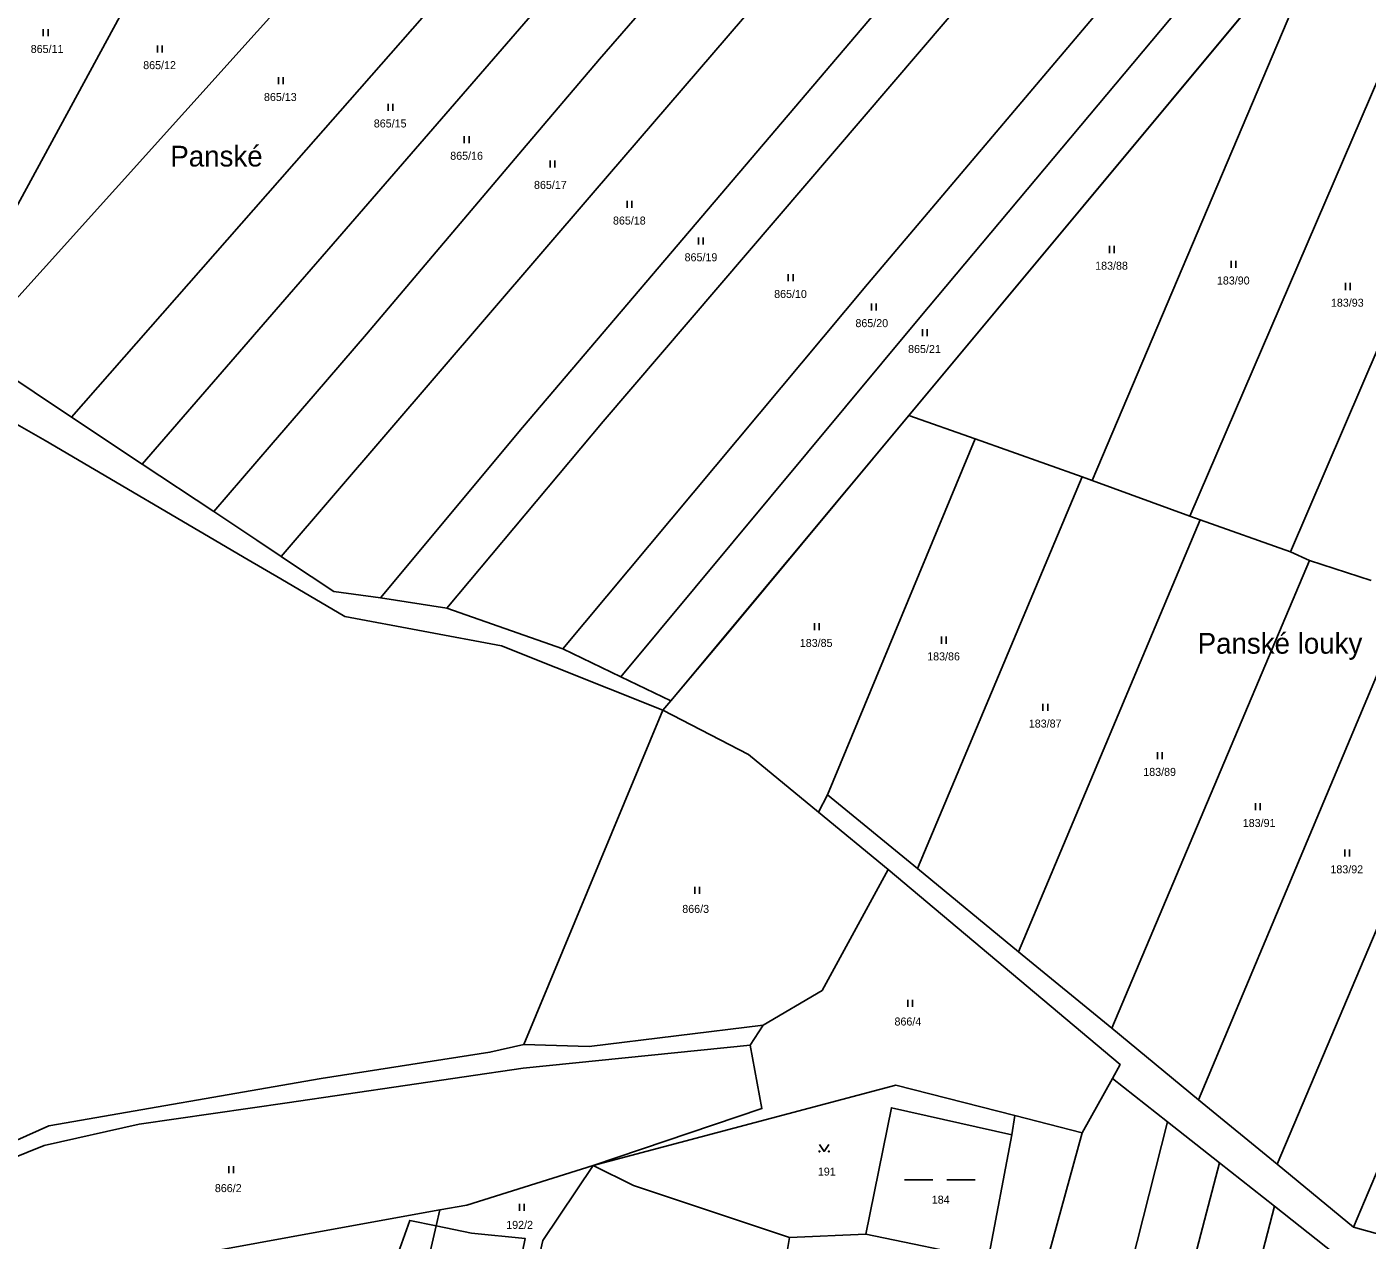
# Model space of a CAD drawing. Extents: x -7483133 to -743169, y -11317770 to -1127091.
# Drawn here: x -747208.1 to -746923.3, y -1132079.1 to -1131821.3 of the extents above; entities that cross this region are included whole.
import ezdxf

# ---------------------------------------------------------------- set-up
doc = ezdxf.new("R2010")
doc.units = 0
for name, color, linetype in [('Hranice parcel', 7, 'Continuous'), ('Parcelní čísla', 7, 'Continuous'), ('Pop  PČ popisy', 7, 'Continuous'), ('Vrstva 55', 7, 'Continuous'), ('Značky kultur', 7, 'Continuous')]:
    doc.layers.add(name, color=color, linetype=linetype)

msp = doc.modelspace()

# ---------------------------------------------------------------- linework, layer by layer
at = {"layer": 'Hranice parcel'}
for p, q in [((-747224.99, -1131886.58), (-747166.79, -1131779.35)), ((-746941.23, -1131808.49), (-747020.64, -1131903.85)), ((-746941.23, -1131808.49), (-747020.64, -1131903.85)), ((-746981.68, -1131917.67), (-746936.15, -1131810.26)), ((-746960.97, -1131925.24), (-746914.68, -1131817.75)), ((-746939.54, -1131932.81), (-746893.39, -1131825.18)), ((-747198.55, -1131904.18), (-747220.07, -1131889.85)), ((-747183.54, -1131914.17), (-747198.55, -1131904.18)), ((-747006.59, -1131908.83), (-747020.64, -1131903.85)), ((-747037.94, -1131984.45), (-747006.59, -1131908.83)), ((-746983.85, -1131916.9), (-747006.59, -1131908.83)), ((-747168.35, -1131924.28), (-747183.54, -1131914.17)), ((-747018.84, -1132000.14), (-746983.85, -1131916.9)), ((-746981.68, -1131917.67), (-746983.85, -1131916.9)), ((-746960.97, -1131925.24), (-746981.68, -1131917.67)), ((-746958.75, -1131926.02), (-746960.97, -1131925.24)), ((-746997.36, -1132017.78), (-746958.75, -1131926.02)), ((-746939.54, -1131932.81), (-746958.75, -1131926.02)), ((-746935.54, -1131934.66), (-746939.54, -1131932.81)), ((-746977.55, -1132034.06), (-746935.54, -1131934.66)), ((-746922.41, -1131938.94), (-746935.54, -1131934.66)), ((-747118.82, -1131944.76), (-747132.91, -1131942.59)), ((-746959.07, -1132049.24), (-746913.99, -1131941.79)), ((-747094.15, -1131953.41), (-747118.82, -1131944.76)), ((-746942.38, -1132062.95), (-746894.14, -1131948.92)), ((-747081.82, -1131959.38), (-747094.15, -1131953.41)), ((-746926.18, -1132076.31), (-746875.37, -1131955.78)), ((-747071.24, -1131964.51), (-747081.82, -1131959.38)), ((-747072.89, -1131966.47), (-747071.24, -1131964.51)), ((-747072.89, -1131966.47), (-747071.24, -1131964.51)), ((-747102.43, -1132037.5), (-747072.89, -1131966.47)), ((-747037.94, -1131984.45), (-747039.86, -1131988.12)), ((-747018.84, -1132000.14), (-747037.94, -1131984.45)), ((-747025.04, -1132000.35), (-747039.86, -1131988.12)), ((-747025.04, -1132000.35), (-747039.86, -1131988.12)), ((-746997.36, -1132017.78), (-747018.84, -1132000.14)), ((-746977.55, -1132034.06), (-746997.36, -1132017.78)), ((-747054.35, -1132037.66), (-747051.63, -1132033.4)), ((-746959.07, -1132049.24), (-746977.55, -1132034.06)), ((-746983.8, -1132056.28), (-746977.4, -1132044.75)), ((-746983.8, -1132056.28), (-746977.4, -1132044.75)), ((-746965.7, -1132053.97), (-746977.4, -1132044.75)), ((-746942.38, -1132062.95), (-746959.07, -1132049.24)), ((-746998.16, -1132052.61), (-746998.74, -1132056.7)), ((-746998.16, -1132052.61), (-746983.8, -1132056.28)), ((-746998.16, -1132052.61), (-746983.8, -1132056.28)), ((-746965.7, -1132053.97), (-746954.65, -1132062.68)), ((-746954.65, -1132062.68), (-746942.98, -1132071.88)), ((-746926.18, -1132076.31), (-746942.38, -1132062.95)), ((-747121.11, -1132076.06), (-747120.33, -1132072.66)), ((-746942.98, -1132071.88), (-746930.38, -1132081.81)), ((-747029.81, -1132077.77), (-747046.01, -1132078.5))]:
    msp.add_line(p, q, dxfattribs=at)
for points in [[(-747198.55, -1131904.18), (-747148.7, -1131847.4), (-747139.41, -1131836.82), (-747075.87, -1131764.45)], [(-747183.54, -1131914.17), (-747152.3, -1131878.12), (-747142.97, -1131867.35), (-747055.5, -1131766.4)], [(-747220.07, -1131889.85), (-747143.77, -1131805.15), (-747134.52, -1131794.88), (-747113.75, -1131771.83)], [(-747168.35, -1131924.28), (-747156.17, -1131910.12), (-747146.8, -1131899.23), (-747135.89, -1131886.55), (-747102.76, -1131847.44), (-747086.37, -1131828.14), (-747038.09, -1131772.55)], [(-747154.03, -1131933.81), (-747087.71, -1131856.54), (-747020.83, -1131778.66)], [(-747132.91, -1131942.59), (-747102.75, -1131906.39), (-747000.3, -1131785.93)], [(-746987.72, -1131790.65), (-747085.59, -1131905.13), (-747118.82, -1131944.76)], [(-747094.15, -1131953.41), (-747029.41, -1131875.97), (-746964.65, -1131799.29)], [(-747081.82, -1131959.38), (-747018.32, -1131883), (-746952.09, -1131804)], [(-747072.89, -1131966.47), (-747107.18, -1131952.81), (-747140.46, -1131946.56), (-747154.1, -1131938.56), (-747161.04, -1131934.49), (-747204.18, -1131909.18), (-747226.07, -1131896.73), (-747265.2, -1131885.54)], [(-747020.64, -1131903.85), (-747058.92, -1131949.83), (-747071.24, -1131964.51)], [(-747020.64, -1131903.85), (-747058.92, -1131949.83), (-747071.24, -1131964.51)], [(-747154.03, -1131933.81), (-747159.2, -1131930.37), (-747168.35, -1131924.28)], [(-747132.91, -1131942.59), (-747142.83, -1131941.27), (-747152.45, -1131934.86), (-747154.03, -1131933.81)], [(-747039.86, -1131988.12), (-747054.69, -1131975.89), (-747072.89, -1131966.47)], [(-747039.86, -1131988.12), (-747054.69, -1131975.89), (-747072.89, -1131966.47)], [(-747051.63, -1132033.4), (-747039.08, -1132026.03), (-747025.04, -1132000.35)], [(-746977.4, -1132044.75), (-746975.74, -1132041.76), (-747025.04, -1132000.35)], [(-746977.4, -1132044.75), (-746975.74, -1132041.76), (-747025.04, -1132000.35)], [(-747051.63, -1132033.4), (-747088.58, -1132037.93), (-747102.43, -1132037.5)], [(-747299.75, -1132213.05), (-747296.34, -1132200.82), (-747282.88, -1132149.41), (-747269.58, -1132097.49), (-747245.11, -1132073.4), (-747236.79, -1132069.7), (-747224.47, -1132064.21), (-747203.37, -1132054.82), (-747145.49, -1132044.7), (-747109.66, -1132039.16), (-747102.43, -1132037.5)], [(-747263.75, -1132103.85), (-747263.48, -1132094.73), (-747243.01, -1132076.52), (-747239.61, -1132074.64), (-747229.58, -1132069.12), (-747226.57, -1132067.9), (-747204.37, -1132058.93), (-747184.23, -1132054.46), (-747152.75, -1132049.88), (-747102.63, -1132042.55), (-747054.35, -1132037.66)], [(-747087.7, -1132063.18), (-747051.87, -1132051.13), (-747054.35, -1132037.66)], [(-747087.7, -1132063.18), (-747023.43, -1132046.16), (-746998.16, -1132052.61)], [(-747087.7, -1132063.18), (-747023.43, -1132046.16), (-746998.16, -1132052.61)], [(-746998.74, -1132056.7), (-747024.36, -1132050.95), (-747029.81, -1132077.77)], [(-747023.94, -1132278.4), (-747013.85, -1132239.65), (-746995.01, -1132168), (-746983.73, -1132125.17), (-746965.7, -1132053.97)], [(-746983.8, -1132056.28), (-747014.12, -1132166.6), (-747033.2, -1132236.24)], [(-747029.81, -1132077.77), (-747003.78, -1132083.21), (-746998.74, -1132056.7)], [(-747010.67, -1132278.83), (-746982.16, -1132168), (-746954.65, -1132062.68)], [(-747120.33, -1132072.66), (-747114.6, -1132071.63), (-747087.7, -1132063.18)], [(-747120.33, -1132072.66), (-747114.6, -1132071.63), (-747087.7, -1132063.18)], [(-747087.7, -1132063.18), (-747098.41, -1132079.17), (-747107.91, -1132120.57)], [(-747087.7, -1132063.18), (-747079.15, -1132067.45), (-747046.01, -1132078.5)], [(-747228.47, -1132092.15), (-747166.2, -1132081.01), (-747144.88, -1132077.08), (-747120.33, -1132072.66)], [(-747228.47, -1132092.15), (-747166.2, -1132081.01), (-747144.88, -1132077.08), (-747120.33, -1132072.66)], [(-746996.68, -1132279.26), (-746973.89, -1132190.98), (-746953.76, -1132113.62), (-746942.98, -1132071.88)], [(-747121.11, -1132076.06), (-747125.84, -1132096.55), (-747139.05, -1132134.66)], [(-747135.55, -1132098.59), (-747132.7, -1132091.74), (-747126.71, -1132074.9), (-747121.11, -1132076.06)], [(-747111.59, -1132124.55), (-747102.16, -1132078.75), (-747113.58, -1132077.61), (-747121.11, -1132076.06)], [(-746908.56, -1132077.75), (-746920.27, -1132077.92), (-746926.18, -1132076.31)], [(-747046.01, -1132078.5), (-747047.24, -1132085.76), (-747050.38, -1132097.04), (-747062.93, -1132151.14), (-747110.31, -1132131.58), (-747107.91, -1132120.57)]]:
    msp.add_lwpolyline(points, dxfattribs=at)
at = {"layer": 'Vrstva 55'}
msp.add_lwpolyline([(-746891.21, -1131727.46), (-746894.04, -1131732), (-746896.34, -1131736.09), (-746917.25, -1131771.33), (-746931.04, -1131793.38), (-746938.23, -1131804.89), (-746941.23, -1131808.49), (-747020.64, -1131903.85), (-747071.24, -1131964.51), (-747072.89, -1131966.47)], dxfattribs=at)
at = {"layer": 'Značky kultur'}
for p, q in [((-747204.56, -1131823.27), (-747204.56, -1131821.77)), ((-747203.56, -1131823.27), (-747203.56, -1131821.77)), ((-747180.29, -1131826.71), (-747180.29, -1131825.21)), ((-747179.29, -1131826.71), (-747179.29, -1131825.21)), ((-747154.62, -1131833.48), (-747154.62, -1131831.98)), ((-747153.62, -1131833.48), (-747153.62, -1131831.98)), ((-747131.32, -1131839.1), (-747131.32, -1131837.6)), ((-747130.32, -1131839.1), (-747130.32, -1131837.6)), ((-747115.11, -1131845.97), (-747115.11, -1131844.47)), ((-747114.11, -1131845.97), (-747114.11, -1131844.47)), ((-747096.87, -1131851.14), (-747096.87, -1131849.64)), ((-747095.87, -1131851.14), (-747095.87, -1131849.64)), ((-747080.51, -1131859.73), (-747080.51, -1131858.23)), ((-747079.51, -1131859.73), (-747079.51, -1131858.23)), ((-747065.32, -1131867.53), (-747065.32, -1131866.03)), ((-747064.32, -1131867.53), (-747064.32, -1131866.03)), ((-746977.99, -1131869.33), (-746977.99, -1131867.83)), ((-746976.99, -1131869.33), (-746976.99, -1131867.83)), ((-746952.14, -1131872.47), (-746952.14, -1131870.97)), ((-746951.14, -1131872.47), (-746951.14, -1131870.97)), ((-747046.26, -1131875.33), (-747046.26, -1131873.83)), ((-747045.26, -1131875.33), (-747045.26, -1131873.83)), ((-746927.86, -1131877.19), (-746927.86, -1131875.69)), ((-746926.86, -1131877.19), (-746926.86, -1131875.69)), ((-747028.62, -1131881.53), (-747028.62, -1131880.03)), ((-747027.62, -1131881.53), (-747027.62, -1131880.03)), ((-747017.76, -1131887.03), (-747017.76, -1131885.53)), ((-747016.76, -1131887.03), (-747016.76, -1131885.53)), ((-747040.73, -1131949.48), (-747040.73, -1131947.98)), ((-747039.73, -1131949.48), (-747039.73, -1131947.98)), ((-747013.71, -1131952.34), (-747013.71, -1131950.84)), ((-747012.71, -1131952.34), (-747012.71, -1131950.84)), ((-746992.15, -1131966.61), (-746992.15, -1131965.11)), ((-746991.15, -1131966.61), (-746991.15, -1131965.11)), ((-746967.79, -1131976.88), (-746967.79, -1131975.38)), ((-746966.79, -1131976.88), (-746966.79, -1131975.38)), ((-746946.99, -1131987.73), (-746946.99, -1131986.23)), ((-746945.99, -1131987.73), (-746945.99, -1131986.23)), ((-746927.99, -1131997.58), (-746927.99, -1131996.08)), ((-746926.99, -1131997.58), (-746926.99, -1131996.08)), ((-747066.1, -1132005.49), (-747066.1, -1132003.99)), ((-747065.1, -1132005.49), (-747065.1, -1132003.99)), ((-747020.85, -1132029.49), (-747020.85, -1132027.99)), ((-747019.85, -1132029.49), (-747019.85, -1132027.99)), ((-747165.13, -1132064.87), (-747165.13, -1132063.37)), ((-747164.13, -1132064.87), (-747164.13, -1132063.37)), ((-747021.58, -1132066.27), (-747015.58, -1132066.27)), ((-747012.58, -1132066.27), (-747006.58, -1132066.27)), ((-747103.38, -1132072.88), (-747103.38, -1132071.38)), ((-747102.38, -1132072.88), (-747102.38, -1132071.38))]:
    msp.add_line(p, q, dxfattribs=at)
msp.add_lwpolyline([(-747039.65, -1132058.73), (-747038.65, -1132060.23), (-747037.65, -1132058.73)], dxfattribs=at)
for centre in [(-747039.65, -1132060.23), (-747037.65, -1132060.23)]:
    msp.add_circle(centre, 0.1, dxfattribs=at)

# ---------------------------------------------------------------- texts
at = {"layer": 'Parcelní čísla'}
for s, p in [('865/11', (-747207.24, -1131826.82)), ('865/12', (-747183.34, -1131830.26)), ('865/13', (-747157.68, -1131837.03)), ('865/15', (-747134.34, -1131842.65)), ('865/16', (-747118.1, -1131849.52)), ('865/17', (-747100.3, -1131855.71)), ('865/18', (-747083.52, -1131863.28)), ('865/19', (-747068.3, -1131871.08)), ('183/88', (-746981.06, -1131872.88)), ('183/90', (-746955.19, -1131876.02)), ('865/10', (-747049.27, -1131878.88)), ('183/93', (-746930.96, -1131880.74)), ('865/20', (-747032, -1131885.08)), ('865/21', (-747020.81, -1131890.58)), ('183/85', (-747043.82, -1131953.03)), ('183/86', (-747016.75, -1131955.89)), ('183/87', (-746995.16, -1131970.16)), ('183/89', (-746970.84, -1131980.43)), ('183/91', (-746949.7, -1131991.28)), ('183/92', (-746931.07, -1132001.13)), ('866/3', (-747068.79, -1132009.54)), ('866/4', (-747023.7, -1132033.47)), ('191', (-747039.98, -1132065.36)), ('866/2', (-747168.11, -1132068.87)), ('184', (-747015.78, -1132071.32)), ('192/2', (-747106.2, -1132076.68))]:
    msp.add_text(s, height=1.7, dxfattribs=at).set_placement(p)
at = {"layer": 'Pop  PČ popisy'}
for s, p in [('Panské', (-747177.58, -1131850.95)), ('Panské louky', (-746959.29, -1131954.46))]:
    msp.add_text(s, height=4.4, dxfattribs=at).set_placement(p)

doc.saveas('drawing.dxf')
